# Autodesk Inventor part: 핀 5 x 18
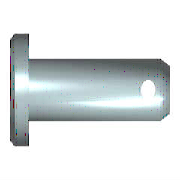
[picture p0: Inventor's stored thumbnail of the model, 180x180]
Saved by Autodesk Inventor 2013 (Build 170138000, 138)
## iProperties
Created: 2012-02
Part Number: 핀 5 x 18
Material: 강철
Description: 머리가 있는 클레비스 핀
Document SubType Name: Modeling
Standard: ISO 2341
Designer: test
Standard Revision: Second edition 1986-11-01
Standards Organization: ISO
Language: ko-KR
Size Designation: B - 5 x 18
Categories: <MemberInstance><Categories><Category DisplayName="조임쇠" InternalName="e4da775c-781d-43d5-af7c-5136215cf5a6" Mnemonic="FSTN"><Category DisplayName="핀" InternalNa
Density: 7.85 g/cm^3
IsCustomPart: 1
Author: test
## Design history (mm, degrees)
sketch "스케치1"
  geometry: L1 (-1.6, 0)-(-1.6, 4); L2 (-1.6, 4)-(0, 4); L3 (0, 4)-(0, 2.5); L4 (0, 2.5)-(18, 2.5); L5 (18, 2.5)-(18, 0); L6 (-1.6, 0)-(18, 0); L7 (-4, 0)-(17, 0) reference; L8 (0, -0.98)-(0, 3.08) reference; C1 r 0.6 at (15.1, 0)
  constraints: 12 end point, 3 parallel, 2 collinear, 2 perpendicular, 1 centre point, 1 point on line, 1 vertical
  dimensions: "d0" = 5 diameter of L4 L6 (= NND); "d1" = 8 diameter of L2 L6 (= KOD); "d2" = 1.6 distance of L1.end L2.end (= KOH); "d3" = 18 distance of L3.end L4.end (= NLG); "d5" = 2.9 distance from line of L5 C1.centre (= DIST); "d6" = 1.2 diameter of C1 (= BOR)
revolve "본체" stored, may be unused: angle "d4" = 90 deg
extrude "구멍" cut sketch "스케치1" stored distance "d7" = 5 (= NND); taper "d8" = 0 deg
workaxis "Work Axis1"
workplane "Work Plane1"
sketch "스케치2"
  geometry: L1 (-18, 1.345)-(-16, 2.5) reference; L2 (-16, 2.5)-(-15.7, 2.5) reference; L3 (-15.7, 2.5)-(-15.7, -2.5) reference; L4 (-15.7, -2.5)-(-16, -2.5) reference; L5 (-16, -2.5)-(-18, -1.345) reference; L6 (-18, -1.345)-(-18, 1.345) reference; L7 (0.6, 4)-(1.6, 3) reference; L8 (1.6, 3)-(1.6, -3) reference; L9 (1.6, -3)-(0.6, -4) reference; L10 (0.6, -4)-(0, -4) reference; L11 (0, -4)-(0, -2.5) reference; L12 (0, -2.5)-(-14.5, -2.5) reference; L13 (-14.5, -2.5)-(-14.5, 2.5) reference; L14 (-14.5, 2.5)-(0, 2.5) reference; L15 (0, 2.5)-(0, 4) reference; L16 (0, 4)-(0.6, 4) reference; 1 further point
  node "절단 모서리 투영1"
sketch "스케치3"
  geometry: L1 (-1.6, 3)-(-0.6, 4) reference; L2 (-0.6, 4)-(0, 4) reference; L3 (0, 4)-(0, 2.5) reference; L4 (0, 2.5)-(16, 2.5) reference; L5 (16, 2.5)-(18, 1.345) reference; L6 (18, 1.345)-(18, -1.345) reference; L7 (18, -1.345)-(16, -2.5) reference; L8 (16, -2.5)-(0, -2.5) reference; L9 (0, -2.5)-(0, -4) reference; L10 (0, -4)-(-0.6, -4) reference; L11 (-0.6, -4)-(-1.6, -3) reference; L12 (-1.6, -3)-(-1.6, 3) reference; C1 r 0.6 at (15.1, 0) reference; 1 further point
  node "절단 모서리 투영2"
node "작업 평면4"
sketch "스케치4"
  geometry: L1 (-18, 1.345)-(-16, 2.5) reference; L2 (-16, 2.5)-(-15.7, 2.5) reference; L3 (-15.7, 2.5)-(-15.7, -2.5) reference; L4 (-15.7, -2.5)-(-16, -2.5) reference; L5 (-16, -2.5)-(-18, -1.345) reference; L6 (-18, -1.345)-(-18, 1.345) reference; L7 (0.6, 4)-(1.6, 3) reference; L8 (1.6, 3)-(1.6, -3) reference; L9 (1.6, -3)-(0.6, -4) reference; L10 (0.6, -4)-(0, -4) reference; L11 (0, -4)-(0, -2.5) reference; L12 (0, -2.5)-(-14.5, -2.5) reference; L13 (-14.5, -2.5)-(-14.5, 2.5) reference; L14 (-14.5, 2.5)-(0, 2.5) reference; L15 (0, 2.5)-(0, 4) reference; L16 (0, 4)-(0.6, 4) reference; L17 (-18, 1.345)-(-16, 2.5) reference; L18 (-16, 2.5)-(-15.7, 2.5) reference; L19 (-15.7, 2.5)-(-15.7, -2.5) reference; L20 (-15.7, -2.5)-(-16, -2.5) reference; L21 (-16, -2.5)-(-18, -1.345) reference; L22 (-18, -1.345)-(-18, 1.345) reference; L23 (0.6, 4)-(1.6, 3) reference; L24 (1.6, 3)-(1.6, -3) reference; L25 (1.6, -3)-(0.6, -4) reference; L26 (0.6, -4)-(0, -4) reference; L27 (0, -4)-(0, -2.5) reference; L28 (0, -2.5)-(-14.5, -2.5) reference; L29 (-14.5, -2.5)-(-14.5, 2.5) reference; L30 (-14.5, 2.5)-(0, 2.5) reference; L31 (0, 2.5)-(0, 4) reference; L32 (0, 4)-(0.6, 4) reference; 1 further point
  node "절단 모서리 투영3"
  node "절단 모서리 투영4"
node "작업 평면5"
body "Solid1"
chamfer "모따기1" distance "d9" = 1 (= PHH2); stored, may be unused: angle "d10" = 45 deg (= FAWI2), second distance "d16" = 1 (= PHH2)
chamfer "모따기2" distance "d11" = 2 (= PHH1); stored, may be unused: angle "d12" = 30 deg (= FAWI1), second distance "d17" = 2 (= PHH1)
other parameters: "PHH1" = 2 [user parameter; used in 2 equation terms], "PHH2" = 1 [user parameter; used in 2 equation terms], "KOD" = 8 [user parameter; used in 1 equation term], "KOH" = 1.6 [user parameter; used in 1 equation term], "NND" = 5 [user parameter; used in 2 equation terms], "FAWI1" = 30 deg [user parameter; used in 1 equation term], "FAWI2" = 45 deg [user parameter; used in 1 equation term], "DIST" = 2.9 [user parameter; used in 1 equation term], "BOR" = 1.2 [user parameter; used in 1 equation term], "NLG" = 18 [user parameter; used in 1 equation term], "d13" = 0, "d14" = 0, "d27" = 0, "d28" = 0, "d29" = 0, "d30" = 0, "d31" = 0, "d32" = 15.1
